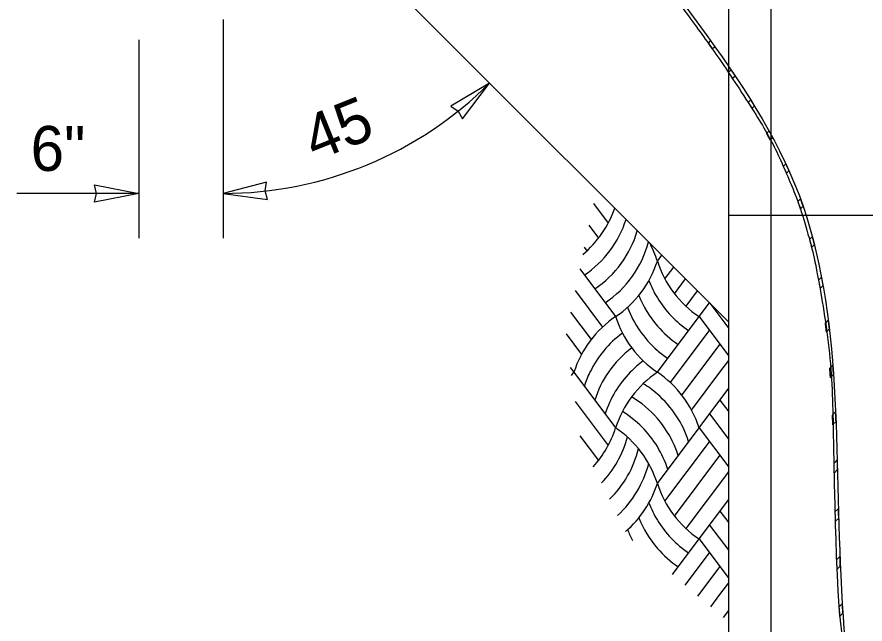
# Model space of a CAD drawing. Extents: x 99862 to 103151, y 100000 to 102076.
# Drawn here: x 101396.9 to 101698.8, y 100863.1 to 101079.4 of the extents above; entities that cross this region are included whole.
import ezdxf

# ---------------------------------------------------------------- set-up
doc = ezdxf.new("R2010")
doc.units = 0
for name, color, linetype in [('Level 10', 7, 'Continuous'), ('Level 12', 7, 'Continuous'), ('Level 15', 7, 'Continuous'), ('Level 2', 7, 'Continuous'), ('Level 20', 7, 'Continuous'), ('Level 5', 7, 'Continuous'), ('Level 7', 7, 'Continuous')]:
    doc.layers.add(name, color=color, linetype=linetype)

msp = doc.modelspace()

# ---------------------------------------------------------------- linework, layer by layer
at = {"layer": 'Level 10'}
msp.add_line((101665.29, 101195.71), (101665.29, 100580.72), dxfattribs=at)
msp.add_line((101665.29, 101195.71), (101665.29, 100580.72), dxfattribs=at)
at = {"layer": 'Level 12'}
for p, q in [((101643.85, 101070.98), (101642.93, 101070.06)), ((101643.85, 101070.98), (101642.93, 101070.06)), ((101644.4, 101067.99), (101645.32, 101068.91)), ((101644.4, 101067.99), (101645.32, 101068.91)), ((101651.12, 101060.57), (101650.19, 101059.64)), ((101651.12, 101060.57), (101650.19, 101059.64)), ((101651.62, 101057.53), (101652.54, 101058.46)), ((101651.62, 101057.53), (101652.54, 101058.46)), ((101658.11, 101049.88), (101657.17, 101048.95)), ((101658.11, 101049.88), (101657.17, 101048.95)), ((101658.53, 101046.76), (101659.46, 101047.7)), ((101658.53, 101046.76), (101659.46, 101047.7)), ((101664.68, 101038.77), (101663.73, 101037.83)), ((101664.68, 101038.77), (101663.73, 101037.83)), ((101664.98, 101035.54), (101665.93, 101036.49)), ((101664.98, 101035.54), (101665.93, 101036.49)), ((101670.67, 101027.09), (101669.7, 101026.12)), ((101670.67, 101027.09), (101669.7, 101026.12)), ((101670.81, 101023.69), (101671.78, 101024.66)), ((101670.81, 101023.69), (101671.78, 101024.66)), ((101675.86, 101014.6), (101674.86, 101013.59)), ((101675.86, 101014.6), (101674.86, 101013.59)), ((101675.77, 101010.97), (101676.78, 101011.99)), ((101675.77, 101010.97), (101676.78, 101011.99)), ((101680.09, 101001.15), (101679.04, 101000.1)), ((101680.09, 101001.15), (101679.04, 101000.1)), ((101679.76, 100997.28), (101680.82, 100998.35)), ((101679.76, 100997.28), (101680.82, 100998.35)), ((101683.36, 100986.75), (101682.26, 100985.65)), ((101683.36, 100986.75), (101682.26, 100985.65)), ((101682.8, 100982.65), (101683.91, 100983.76)), ((101682.8, 100982.65), (101683.91, 100983.76)), ((101685.75, 100971.45), (101684.59, 100970.3)), ((101685.75, 100971.45), (101684.59, 100970.3)), ((101684.96, 100967.13), (101686.13, 100968.3)), ((101684.96, 100967.13), (101686.13, 100968.3)), ((101687.35, 100955.38), (101686.15, 100954.18)), ((101687.35, 100955.38), (101686.15, 100954.18)), ((101686.38, 100950.87), (101687.59, 100952.08)), ((101686.38, 100950.87), (101687.59, 100952.08)), ((101688.34, 100938.69), (101687.1, 100937.45)), ((101688.34, 100938.69), (101687.1, 100937.45)), ((101687.24, 100934.05), (101688.48, 100935.29)), ((101687.24, 100934.05), (101688.48, 100935.29)), ((101688.92, 100921.6), (101687.67, 100920.34)), ((101688.92, 100921.6), (101687.67, 100920.34)), ((101687.76, 100916.89), (101689.01, 100918.15)), ((101687.76, 100916.89), (101689.01, 100918.15)), ((101689.35, 100904.34), (101688.09, 100903.09)), ((101689.35, 100904.34), (101688.09, 100903.09)), ((101688.18, 100899.64), (101689.44, 100900.9)), ((101688.18, 100899.64), (101689.44, 100900.9)), ((101689.87, 100887.19), (101688.63, 100885.95)), ((101689.87, 100887.19), (101688.63, 100885.95)), ((101688.77, 100882.55), (101690, 100883.79)), ((101688.77, 100882.55), (101690, 100883.79)), ((101690.71, 100870.35), (101689.5, 100869.14)), ((101690.71, 100870.35), (101689.5, 100869.14)), ((101689.73, 100865.84), (101690.94, 100867.04)), ((101689.73, 100865.84), (101690.94, 100867.04))]:
    msp.add_line(p, q, dxfattribs=at)
for points in [[(101642.93, 101070.06), (101642.93, 101070.06)], [(101642.93, 101070.06), (101642.93, 101070.06)], [(101644.4, 101067.99), (101644.4, 101067.99)], [(101644.4, 101067.99), (101644.4, 101067.99)], [(101650.19, 101059.64), (101650.19, 101059.64)], [(101650.19, 101059.64), (101650.19, 101059.64)], [(101651.62, 101057.53), (101651.62, 101057.53)], [(101651.62, 101057.53), (101651.62, 101057.53)], [(101657.17, 101048.95), (101657.17, 101048.95)], [(101657.17, 101048.95), (101657.17, 101048.95)], [(101658.53, 101046.76), (101658.53, 101046.76)], [(101658.53, 101046.76), (101658.53, 101046.76)], [(101663.73, 101037.83), (101663.73, 101037.83)], [(101663.73, 101037.83), (101663.73, 101037.83)], [(101664.98, 101035.54), (101664.98, 101035.54)], [(101664.98, 101035.54), (101664.98, 101035.54)], [(101669.7, 101026.12), (101669.7, 101026.12)], [(101669.7, 101026.12), (101669.7, 101026.12)], [(101670.81, 101023.69), (101670.81, 101023.69)], [(101670.81, 101023.69), (101670.81, 101023.69)], [(101675.77, 101010.97), (101675.77, 101010.97)], [(101675.77, 101010.97), (101675.77, 101010.97)], [(101679.04, 101000.1), (101679.04, 101000.1)], [(101679.04, 101000.1), (101679.04, 101000.1)], [(101679.76, 100997.28), (101679.76, 100997.28)], [(101679.76, 100997.28), (101679.76, 100997.28)], [(101682.26, 100985.65), (101682.26, 100985.65)], [(101682.26, 100985.65), (101682.26, 100985.65)], [(101682.8, 100982.65), (101682.8, 100982.65)], [(101682.8, 100982.65), (101682.8, 100982.65)], [(101684.59, 100970.3), (101684.59, 100970.3)], [(101684.59, 100970.3), (101684.59, 100970.3)], [(101684.96, 100967.13), (101684.96, 100967.13)], [(101684.96, 100967.13), (101684.96, 100967.13)], [(101686.15, 100954.18), (101686.15, 100954.18)], [(101686.15, 100954.18), (101686.15, 100954.18)], [(101686.38, 100950.87), (101686.38, 100950.87)], [(101686.38, 100950.87), (101686.38, 100950.87)], [(101687.1, 100937.45), (101687.1, 100937.45)], [(101687.1, 100937.45), (101687.1, 100937.45)], [(101687.24, 100934.05), (101687.24, 100934.05)], [(101687.24, 100934.05), (101687.24, 100934.05)], [(101687.67, 100920.34), (101687.67, 100920.34)], [(101687.67, 100920.34), (101687.67, 100920.34)], [(101689.44, 100900.9), (101689.44, 100900.9)], [(101689.44, 100900.9), (101689.44, 100900.9)], [(101689.87, 100887.19), (101689.87, 100887.19)], [(101689.87, 100887.19), (101689.87, 100887.19)], [(101690, 100883.79), (101690, 100883.79)], [(101690, 100883.79), (101690, 100883.79)], [(101690.71, 100870.35), (101690.71, 100870.35)], [(101690.71, 100870.35), (101690.71, 100870.35)], [(101690.94, 100867.04), (101690.94, 100867.04)], [(101690.94, 100867.04), (101690.94, 100867.04)]]:
    msp.add_lwpolyline(points, dxfattribs=at)
for points, degree in [([(101642.93, 101070.06), (101643.42, 101069.37), (101643.91, 101068.68), (101644.4, 101067.99)], 2), ([(101642.93, 101070.06), (101643.42, 101069.37), (101643.91, 101068.68), (101644.4, 101067.99)], 2), ([(101645.32, 101068.91), (101644.83, 101069.6), (101644.34, 101070.29), (101643.85, 101070.98)], 2), ([(101645.32, 101068.91), (101644.83, 101069.6), (101644.34, 101070.29), (101643.85, 101070.98)], 2), ([(101652.54, 101058.46), (101652.07, 101059.16), (101651.6, 101059.87), (101651.12, 101060.57)], 2), ([(101652.54, 101058.46), (101652.07, 101059.16), (101651.6, 101059.87), (101651.12, 101060.57)], 2), ([(101650.19, 101059.64), (101650.67, 101058.94), (101651.14, 101058.24), (101651.62, 101057.53)], 2), ([(101650.19, 101059.64), (101650.67, 101058.94), (101651.14, 101058.24), (101651.62, 101057.53)], 2), ([(101657.17, 101048.95), (101657.63, 101048.22), (101658.08, 101047.49), (101658.53, 101046.76)], 2), ([(101657.17, 101048.95), (101657.63, 101048.22), (101658.08, 101047.49), (101658.53, 101046.76)], 2), ([(101659.46, 101047.7), (101659.01, 101048.43), (101658.56, 101049.15), (101658.11, 101049.88)], 2), ([(101659.46, 101047.7), (101659.01, 101048.43), (101658.56, 101049.15), (101658.11, 101049.88)], 2), ([(101663.73, 101037.83), (101664.15, 101037.07), (101664.57, 101036.3), (101664.98, 101035.54)], 2), ([(101663.73, 101037.83), (101664.15, 101037.07), (101664.57, 101036.3), (101664.98, 101035.54)], 2), ([(101665.93, 101036.49), (101665.52, 101037.25), (101665.1, 101038.02), (101664.68, 101038.77)], 2), ([(101665.93, 101036.49), (101665.52, 101037.25), (101665.1, 101038.02), (101664.68, 101038.77)], 2), ([(101669.7, 101026.12), (101670.08, 101025.31), (101670.44, 101024.5), (101670.81, 101023.69)], 2), ([(101669.7, 101026.12), (101670.08, 101025.31), (101670.44, 101024.5), (101670.81, 101023.69)], 2), ([(101671.78, 101024.66), (101671.42, 101025.47), (101671.05, 101026.28), (101670.67, 101027.09)], 2), ([(101671.78, 101024.66), (101671.42, 101025.47), (101671.05, 101026.28), (101670.67, 101027.09)], 2), ([(101674.86, 101013.59), (101675.17, 101012.72), (101675.47, 101011.85), (101675.77, 101010.97)], 2), ([(101674.86, 101013.59), (101675.17, 101012.72), (101675.47, 101011.85), (101675.77, 101010.97)], 2), ([(101676.78, 101011.99), (101676.48, 101012.86), (101676.18, 101013.73), (101675.86, 101014.6)], 2), ([(101676.78, 101011.99), (101676.48, 101012.86), (101676.18, 101013.73), (101675.86, 101014.6)], 2), ([(101679.04, 101000.1), (101679.29, 100999.16), (101679.53, 100998.23), (101679.76, 100997.28)], 2), ([(101679.04, 101000.1), (101679.29, 100999.16), (101679.53, 100998.23), (101679.76, 100997.28)], 2), ([(101680.82, 100998.35), (101680.58, 100999.28), (101680.34, 101000.22), (101680.09, 101001.15)], 2), ([(101680.82, 100998.35), (101680.58, 100999.28), (101680.34, 101000.22), (101680.09, 101001.15)], 2), ([(101682.26, 100985.65), (101682.43, 100984.74), (101682.59, 100983.83), (101682.77, 100982.82), (101682.78, 100982.73), (101682.8, 100982.65)], 3), ([(101682.26, 100985.65), (101682.43, 100984.74), (101682.59, 100983.83), (101682.77, 100982.82), (101682.78, 100982.73), (101682.8, 100982.65)], 3), ([(101683.91, 100983.76), (101683.73, 100984.76), (101683.55, 100985.75), (101683.36, 100986.75)], 2), ([(101683.91, 100983.76), (101683.73, 100984.76), (101683.55, 100985.75), (101683.36, 100986.75)], 2), ([(101684.59, 100970.3), (101684.72, 100969.25), (101684.84, 100968.19), (101684.96, 100967.13)], 2), ([(101684.59, 100970.3), (101684.72, 100969.25), (101684.84, 100968.19), (101684.96, 100967.13)], 2), ([(101686.13, 100968.3), (101686, 100969.35), (101685.88, 100970.4), (101685.75, 100971.45)], 2), ([(101686.13, 100968.3), (101686, 100969.35), (101685.88, 100970.4), (101685.75, 100971.45)], 2), ([(101687.59, 100952.08), (101687.51, 100953.18), (101687.43, 100954.28), (101687.35, 100955.38)], 2), ([(101687.59, 100952.08), (101687.51, 100953.18), (101687.43, 100954.28), (101687.35, 100955.38)], 2), ([(101686.15, 100954.18), (101686.23, 100953.08), (101686.31, 100951.98), (101686.38, 100950.87)], 2), ([(101686.15, 100954.18), (101686.23, 100953.08), (101686.31, 100951.98), (101686.38, 100950.87)], 2), ([(101687.1, 100937.45), (101687.15, 100936.32), (101687.2, 100935.19), (101687.24, 100934.05)], 2), ([(101687.1, 100937.45), (101687.15, 100936.32), (101687.2, 100935.19), (101687.24, 100934.05)], 2), ([(101688.48, 100935.29), (101688.43, 100936.43), (101688.39, 100937.56), (101688.34, 100938.69)], 2), ([(101688.48, 100935.29), (101688.43, 100936.43), (101688.39, 100937.56), (101688.34, 100938.69)], 2), ([(101689.01, 100918.15), (101688.98, 100919.3), (101688.95, 100920.45), (101688.92, 100921.6)], 2), ([(101689.01, 100918.15), (101688.98, 100919.3), (101688.95, 100920.45), (101688.92, 100921.6)], 2), ([(101687.67, 100920.34), (101687.7, 100919.19), (101687.73, 100918.04), (101687.76, 100916.89)], 2), ([(101687.67, 100920.34), (101687.7, 100919.19), (101687.73, 100918.04), (101687.76, 100916.89)], 2), ([(101689.44, 100900.9), (101689.41, 100902.05), (101689.38, 100903.2), (101689.35, 100904.34)], 2), ([(101689.44, 100900.9), (101689.41, 100902.05), (101689.38, 100903.2), (101689.35, 100904.34)], 2), ([(101688.09, 100903.09), (101688.11, 100902.49), (101688.12, 100901.89), (101688.15, 100900.74), (101688.17, 100900.19), (101688.18, 100899.64)], 3), ([(101688.09, 100903.09), (101688.11, 100902.49), (101688.12, 100901.89), (101688.15, 100900.74), (101688.17, 100900.19), (101688.18, 100899.64)], 3), ([(101688.63, 100885.95), (101688.67, 100884.82), (101688.72, 100883.68), (101688.77, 100882.55)], 2), ([(101688.63, 100885.95), (101688.67, 100884.82), (101688.72, 100883.68), (101688.77, 100882.55)], 2), ([(101690, 100883.79), (101689.96, 100884.92), (101689.91, 100886.05), (101689.87, 100887.19)], 2), ([(101690, 100883.79), (101689.96, 100884.92), (101689.91, 100886.05), (101689.87, 100887.19)], 2), ([(101690.94, 100867.04), (101690.86, 100868.14), (101690.79, 100869.25), (101690.71, 100870.35)], 2), ([(101690.94, 100867.04), (101690.86, 100868.14), (101690.79, 100869.25), (101690.71, 100870.35)], 2), ([(101689.5, 100869.14), (101689.58, 100868.04), (101689.65, 100866.94), (101689.73, 100865.84)], 2), ([(101689.5, 100869.14), (101689.58, 100868.04), (101689.65, 100866.94), (101689.73, 100865.84)], 2)]:
    msp.add_open_spline(points, degree=degree, dxfattribs=at)
at = {"layer": 'Level 15'}
for p, q in [((101470.29, 101078.46), (101470.29, 101000.55)), ((101470.29, 101078.46), (101470.29, 101000.55)), ((101440.29, 101071.21), (101440.29, 101000.55)), ((101440.29, 101071.21), (101440.29, 101000.55)), ((101440.29, 101016.55), (101396.95, 101016.55)), ((101440.29, 101016.55), (101396.95, 101016.55))]:
    msp.add_line(p, q, dxfattribs=at)
for points in [[(101565.16, 101055.84), (101551.38, 101047.66), (101553.98, 101045.85), (101555.49, 101043.06)], [(101565.16, 101055.84), (101551.38, 101047.66), (101553.98, 101045.85), (101555.49, 101043.06)], [(101440.29, 101016.55), (101424.56, 101013.46), (101425.29, 101016.55), (101424.56, 101019.63)], [(101440.29, 101016.55), (101424.56, 101013.46), (101425.29, 101016.55), (101424.56, 101019.63)], [(101470.29, 101016.55), (101486.16, 101014.35), (101485.26, 101017.39), (101485.81, 101020.51)], [(101470.29, 101016.55), (101486.16, 101014.35), (101485.26, 101017.39), (101485.81, 101020.51)]]:
    msp.add_lwpolyline(points, close=True, dxfattribs=at)
msp.add_arc((101470.29, 101150.71), 134.17, 270, 315, dxfattribs=at)
msp.add_arc((101470.29, 101150.71), 134.17, 270, 315, dxfattribs=at)
at = {"layer": 'Level 2'}
for p, q in [((101650.29, 100970.72), (101470.29, 101150.71)), ((101650.29, 101008.63), (101650.29, 101113.63)), ((101830.29, 101008.63), (101650.29, 101008.63)), ((101650.29, 100550.72), (101650.29, 101008.63))]:
    msp.add_line(p, q, dxfattribs=at)
at = {"layer": 'Level 5'}
for p, q in [((101602.1, 101012.91), (101607.36, 101005.89)), ((101602.1, 101012.91), (101607.36, 101005.89)), ((101600.49, 101005.17), (101603.92, 101000.59)), ((101600.49, 101005.17), (101603.92, 101000.59)), ((101598.87, 100997.43), (101599.84, 100996.12)), ((101598.87, 100997.43), (101599.84, 100996.12)), ((101624.89, 100992.43), (101626.47, 100994.53)), ((101624.89, 100992.43), (101626.47, 100994.53)), ((101597.25, 100989.69), (101610.04, 100972.63)), ((101597.25, 100989.69), (101610.04, 100972.63)), ((101627.56, 100986.09), (101630.71, 100990.29)), ((101627.56, 100986.09), (101630.71, 100990.29)), ((101631, 100980.79), (101634.95, 100986.05)), ((101631, 100980.79), (101634.95, 100986.05)), ((101595.63, 100981.95), (101605.38, 100968.94)), ((101595.63, 100981.95), (101605.38, 100968.94)), ((101635.08, 100976.32), (101639.19, 100981.81)), ((101635.08, 100976.32), (101639.19, 100981.81)), ((101639.74, 100972.63), (101643.44, 100977.56)), ((101639.74, 100972.63), (101643.44, 100977.56)), ((101643.53, 100977.48), (101650.29, 100968.46)), ((101643.53, 100977.48), (101650.29, 100968.46)), ((101594.01, 100974.21), (101601.31, 100964.47)), ((101594.01, 100974.21), (101601.31, 100964.47)), ((101624.89, 100952.83), (101639.74, 100972.63)), ((101624.89, 100952.83), (101639.74, 100972.63)), ((101639.74, 100972.63), (101650.29, 100958.56)), ((101639.74, 100972.63), (101650.29, 100958.56)), ((101632.31, 100952.83), (101643.45, 100967.68)), ((101632.31, 100952.83), (101643.45, 100967.68)), ((101592.39, 100966.47), (101597.86, 100959.16)), ((101592.39, 100966.47), (101597.86, 100959.16)), ((101639.74, 100952.83), (101647.16, 100962.73)), ((101639.74, 100952.83), (101647.16, 100962.73)), ((101647.16, 100952.83), (101650.29, 100957)), ((101647.16, 100952.83), (101650.29, 100957)), ((101593.9, 100954.55), (101595.19, 100952.83)), ((101593.9, 100954.55), (101595.19, 100952.83)), ((101594.3, 100951.65), (101595.19, 100952.83)), ((101594.3, 100951.65), (101595.19, 100952.83)), ((101595.19, 100952.83), (101610.04, 100933.03)), ((101595.19, 100952.83), (101610.04, 100933.03)), ((101629.54, 100949.14), (101632.31, 100952.83)), ((101629.54, 100949.14), (101632.31, 100952.83)), ((101633.62, 100944.67), (101639.74, 100952.83)), ((101633.62, 100944.67), (101639.74, 100952.83)), ((101637.06, 100939.36), (101647.16, 100952.83)), ((101637.06, 100939.36), (101647.16, 100952.83)), ((101639.74, 100933.03), (101650.29, 100947.1)), ((101639.74, 100933.03), (101650.29, 100947.1)), ((101647.16, 100942.93), (101650.29, 100938.76)), ((101647.16, 100942.93), (101650.29, 100938.76)), ((101595.6, 100942.39), (101607.36, 100926.7)), ((101595.6, 100942.39), (101607.36, 100926.7)), ((101643.45, 100937.98), (101650.29, 100928.86)), ((101643.45, 100937.98), (101650.29, 100928.86)), ((101624.89, 100913.23), (101639.74, 100933.03)), ((101624.89, 100913.23), (101639.74, 100933.03)), ((101639.74, 100933.03), (101650.29, 100918.96)), ((101639.74, 100933.03), (101650.29, 100918.96)), ((101597.29, 100930.22), (101603.92, 100921.39)), ((101597.29, 100930.22), (101603.92, 100921.39)), ((101627.56, 100906.9), (101643.45, 100928.08)), ((101627.56, 100906.9), (101643.45, 100928.08)), ((101631, 100901.59), (101647.16, 100923.13)), ((101631, 100901.59), (101647.16, 100923.13)), ((101635.08, 100897.13), (101650.29, 100917.4)), ((101635.08, 100897.13), (101650.29, 100917.4)), ((101639.74, 100893.43), (101650.29, 100907.5)), ((101639.74, 100893.43), (101650.29, 100907.5)), ((101647.16, 100903.33), (101650.29, 100899.16)), ((101647.16, 100903.33), (101650.29, 100899.16)), ((101643.45, 100898.38), (101650.29, 100889.27)), ((101643.45, 100898.38), (101650.29, 100889.27)), ((101630.25, 100880.78), (101639.74, 100893.43)), ((101630.25, 100880.78), (101639.74, 100893.43)), ((101639.74, 100893.43), (101650.29, 100879.37)), ((101639.74, 100893.43), (101650.29, 100879.37)), ((101634.79, 100876.94), (101643.45, 100888.48)), ((101634.79, 100876.94), (101643.45, 100888.48)), ((101639.74, 100873.63), (101647.16, 100883.53)), ((101639.74, 100873.63), (101647.16, 100883.53)), ((101647.16, 100873.63), (101650.29, 100877.8)), ((101647.16, 100873.63), (101650.29, 100877.8)), ((101639.33, 100873.09), (101639.74, 100873.63)), ((101639.33, 100873.09), (101639.74, 100873.63)), ((101643.87, 100869.25), (101647.16, 100873.63)), ((101643.87, 100869.25), (101647.16, 100873.63)), ((101648.41, 100865.4), (101650.29, 100867.9)), ((101648.41, 100865.4), (101650.29, 100867.9))]:
    msp.add_line(p, q, dxfattribs=at)
for centre, start, end in [((101574.23, 101023.62), 309.8538, 340.8322), ((101574.23, 101023.62), 309.8538, 340.8322), ((101577.94, 101018.67), 303.9036, 342.3241), ((101577.94, 101018.67), 303.9036, 342.3241), ((101581.65, 101013.72), 303.9036, 343.8363), ((101581.65, 101013.72), 303.9036, 343.8363), ((101585.37, 101008.77), 303.9036, 345.3708), ((101585.37, 101008.77), 303.9036, 345.3708), ((101589.08, 100981.04), 17.6434, 28.2389), ((101589.08, 100981.04), 17.6434, 28.2389), ((101589.08, 101003.82), 303.9036, 342.3566), ((101589.08, 101003.82), 303.9036, 342.3566), ((101660.7, 101003.82), 197.6435, 236.0964), ((101660.7, 101003.82), 197.6435, 236.0964), ((101656.98, 100998.87), 200.8778, 211.332), ((101656.98, 100998.87), 200.8778, 211.332), ((101653.27, 100993.92), 201.4344, 220.9416), ((101653.27, 100993.92), 201.4344, 220.9416), ((101656.98, 100998.87), 211.3319, 236.0964), ((101656.98, 100998.87), 211.3319, 236.0964), ((101649.56, 100988.97), 200.2432, 228.9599), ((101649.56, 100988.97), 200.2432, 228.9599), ((101631, 100941.44), 123.9036, 162.3566), ((101631, 100941.44), 123.9036, 162.3566), ((101645.85, 100984.02), 197.6434, 236.0964), ((101645.85, 100984.02), 197.6434, 236.0964), ((101634.71, 100936.49), 126.3063, 154.2266), ((101634.71, 100936.49), 126.3063, 154.2266), ((101653.27, 100993.92), 220.9415, 236.0964), ((101653.27, 100993.92), 220.9415, 236.0964), ((101638.42, 100931.54), 127.1006, 145.4911), ((101638.42, 100931.54), 127.1006, 145.4911), ((101649.56, 100988.97), 228.9599, 236.0964), ((101649.56, 100988.97), 228.9599, 236.0964), ((101642.14, 100926.59), 126.331, 135.7128), ((101642.14, 100926.59), 126.331, 135.7128), ((101634.71, 100936.49), 154.2265, 162.3566), ((101634.71, 100936.49), 154.2265, 162.3566), ((101638.42, 100931.54), 145.491, 162.3566), ((101638.42, 100931.54), 145.491, 162.3566), ((101642.14, 100926.59), 135.7127, 162.3566), ((101642.14, 100926.59), 135.7127, 162.3566), ((101645.85, 100921.64), 123.9036, 162.3566), ((101645.85, 100921.64), 123.9036, 162.3566), ((101603.93, 100921.64), 17.6434, 56.0963), ((101603.93, 100921.64), 17.6434, 56.0963), ((101600.21, 100916.69), 48.9597, 58.5465), ((101600.21, 100916.69), 48.9597, 58.5465), ((101596.5, 100911.74), 40.9413, 59.3021), ((101596.5, 100911.74), 40.9413, 59.3021), ((101600.21, 100916.69), 17.6434, 48.9597), ((101600.21, 100916.69), 17.6434, 48.9597), ((101592.79, 100906.79), 31.3316, 58.4874), ((101592.79, 100906.79), 31.3316, 58.4874), ((101596.5, 100911.74), 17.6434, 40.9414), ((101596.5, 100911.74), 17.6434, 40.9414), ((101574.23, 100944.42), 317.8142, 342.3566), ((101574.23, 100944.42), 317.8142, 342.3566), ((101589.08, 100901.84), 17.6434, 56.0964), ((101589.08, 100901.84), 17.6434, 56.0964), ((101577.94, 100939.47), 316.0142, 345.0113), ((101577.94, 100939.47), 316.0142, 345.0113), ((101581.65, 100934.52), 314.234, 346.3199), ((101581.65, 100934.52), 314.234, 346.3199), ((101592.79, 100906.79), 17.6434, 31.3317), ((101592.79, 100906.79), 17.6434, 31.3317), ((101585.37, 100929.57), 312.4712, 345.7713), ((101585.37, 100929.57), 312.4712, 345.7713), ((101589.08, 100924.62), 310.7238, 342.3566), ((101589.08, 100924.62), 310.7238, 342.3566), ((101660.7, 100924.62), 197.6435, 236.0964), ((101660.7, 100924.62), 197.6435, 236.0964), ((101656.98, 100919.67), 200.8778, 211.332), ((101656.98, 100919.67), 200.8778, 211.332), ((101653.27, 100914.72), 201.4344, 220.9416), ((101653.27, 100914.72), 201.4344, 220.9416), ((101656.98, 100919.67), 211.3319, 236.0964), ((101656.98, 100919.67), 211.3319, 236.0964), ((101649.56, 100909.77), 200.2432, 206.7944), ((101649.56, 100909.77), 200.2432, 206.7944), ((101653.27, 100914.72), 220.9415, 236.0964), ((101653.27, 100914.72), 220.9415, 236.0964)]:
    msp.add_arc(centre, 37.58, start, end, dxfattribs=at)
at = {"layer": 'Level 7'}
for points in [[(101578.49, 101399.22), (101578.89, 101348.3), (101579.2, 101308.33), (101580.53, 101243.91), (101581.56, 101219.64), (101585.25, 101181.08), (101587.92, 101166.78), (101593.85, 101148.19), (101596.15, 101142.47), (101601.49, 101131.25), (101604.54, 101125.73), (101614.5, 101109.3), (101622.21, 101098.56), (101637.96, 101076.96), (101646, 101066.11), (101660.64, 101043.82), (101667.23, 101032.38), (101674.7, 101014.44), (101676.78, 101008.31), (101680.24, 100995.79), (101681.63, 100989.41), (101687.23, 100956.93), (101687.41, 100929.24), (101688.32, 100894.37), (101688.54, 100887.44), (101688.86, 100880.52)], [(101578.49, 101399.22), (101578.89, 101348.3), (101579.2, 101308.33), (101580.53, 101243.91), (101581.56, 101219.64), (101585.25, 101181.08), (101587.92, 101166.78), (101593.85, 101148.19), (101596.15, 101142.47), (101601.49, 101131.25), (101604.54, 101125.73), (101614.5, 101109.3), (101622.21, 101098.56), (101637.96, 101076.96), (101646, 101066.11), (101660.64, 101043.82), (101667.23, 101032.38), (101674.7, 101014.44), (101676.78, 101008.31), (101680.24, 100995.79), (101681.63, 100989.41), (101687.23, 100956.93), (101687.41, 100929.24), (101688.32, 100894.37), (101688.54, 100887.44), (101688.86, 100880.52)], [(101579.76, 101400.85), (101581.19, 101218.42), (101581.71, 101132.87), (101693.98, 101026.9), (101687.89, 100928.49), (101690.15, 100880.46)], [(101579.76, 101400.85), (101581.19, 101218.42), (101581.71, 101132.87), (101693.98, 101026.9), (101687.89, 100928.49), (101690.15, 100880.46)], [(101688.86, 100880.52), (101691.17, 100819.85), (101733.27, 100769.69), (101738.23, 100745.75), (101739.79, 100672.83)], [(101690.15, 100880.56), (101691.28, 100850.83), (101697, 100829.67), (101707.35, 100805.58), (101711.1, 100798.82), (101718.37, 100786.99), (101721.89, 100781.91), (101727.88, 100772.53), (101730.32, 100768.26), (101734.25, 100758.77), (101735.75, 100753.56), (101739.17, 100733.89), (101740.08, 100715.37), (101741.1, 100673.21)]]:
    msp.add_open_spline(points, degree=3, dxfattribs=at)

# ---------------------------------------------------------------- texts
at = {"layer": 'Level 20'}
msp.add_text('45', height=16, rotation=21.8868, dxfattribs=at).set_placement((101503.02, 101027.91))
msp.add_text('6"', height=16, dxfattribs=at).set_placement((101401.82, 101024.55))

doc.saveas('drawing.dxf')
